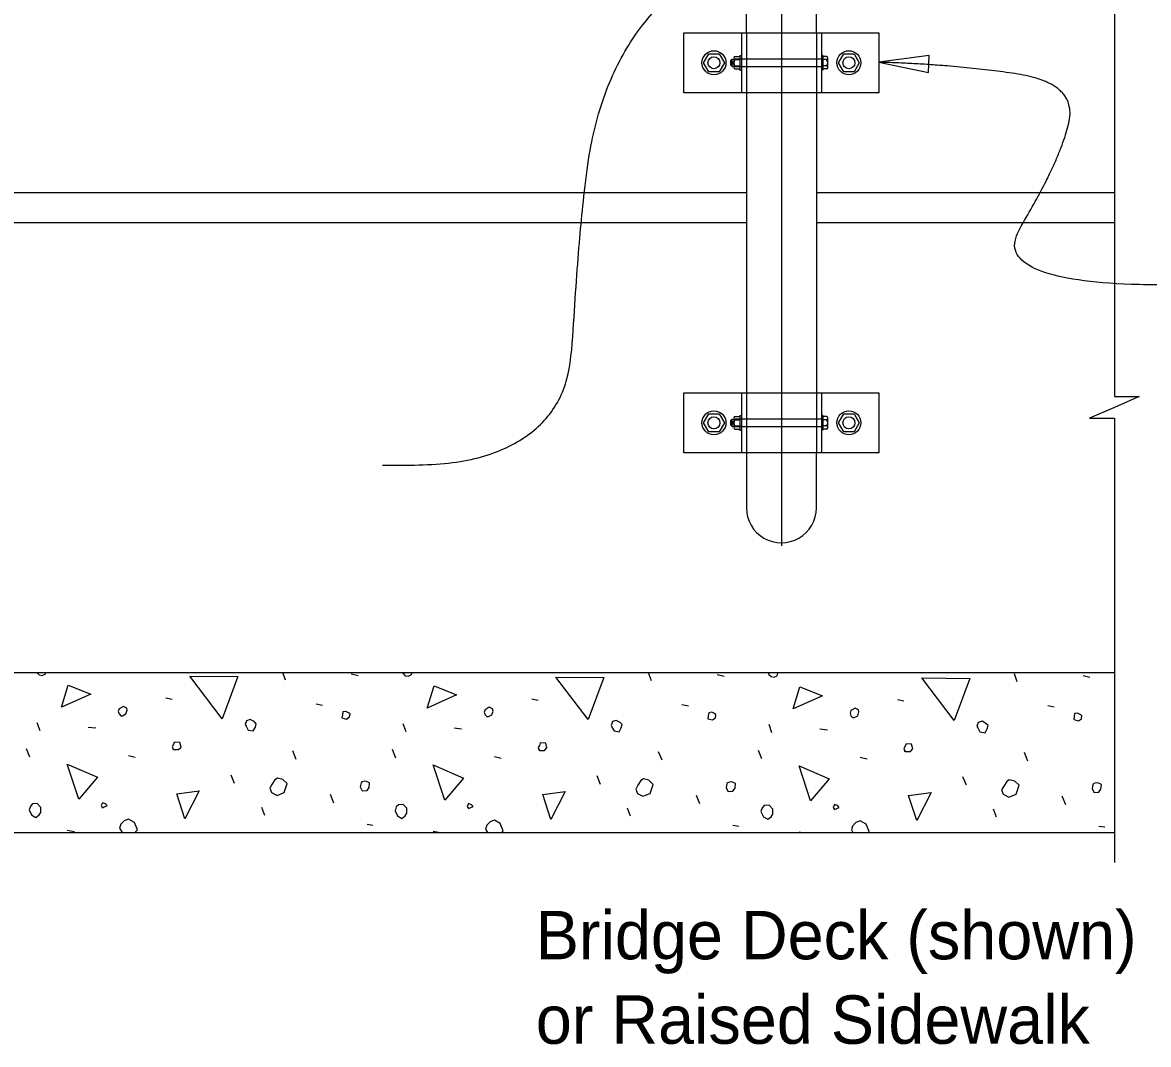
# Model space of a CAD drawing. Extents: x 0 to 72.1, y -7 to 30.
# Drawn here: x 19.062 to 23.751, y 14.64 to 18.897 of the extents above; entities that cross this region are included whole.
import ezdxf

# ---------------------------------------------------------------- set-up
doc = ezdxf.new("R2010")
doc.units = 0
for name, color, linetype in [('AdhocPoint_dp', 7, 'Continuous'), ('Border', 7, 'Continuous'), ('Patterning', 7, 'Continuous'), ('PlotBorder_dp', 7, 'Continuous'), ('SheetBorder_dp', 7, 'Continuous'), ('TextMisc', 7, 'Continuous')]:
    doc.layers.add(name, color=color, linetype=linetype)

msp = doc.modelspace()

# ---------------------------------------------------------------- linework, layer by layer
at = {"layer": 'AdhocPoint_dp'}
for p, q in [((22.0147, 18.7229), (22.0147, 18.735)), ((22.0204, 18.7229), (22.0204, 18.735)), ((22.0147, 17.2229), (22.0147, 17.235)), ((22.0204, 17.2229), (22.0204, 17.235)), ((20.157, 16.1581), (20.1452, 16.1899)), ((20.431, 16.1846), (20.4593, 16.1776)), ((21.6808, 16.1546), (21.6684, 16.1882)), ((21.9548, 16.1811), (21.9831, 16.174)), ((23.2046, 16.151), (23.1922, 16.1846)), ((23.4786, 16.1776), (23.5069, 16.1705)), ((19.6585, 16.0839), (19.685, 16.0786)), ((20.2842, 16.0591), (20.3108, 16.0538)), ((21.1823, 16.0803), (21.2088, 16.075)), ((21.8081, 16.0556), (21.8346, 16.0503)), ((22.7061, 16.0768), (22.7326, 16.0715)), ((23.3319, 16.052), (23.3584, 16.0467)), ((19.1352, 15.946), (19.1228, 15.9796)), ((19.335, 15.9619), (19.3668, 15.9584)), ((20.659, 15.9424), (20.6466, 15.976)), ((20.8588, 15.9584), (20.8906, 15.9548)), ((22.1828, 15.9389), (22.1705, 15.9725)), ((22.3826, 15.9548), (22.4144, 15.9513)), ((19.0928, 15.8364), (19.0786, 15.8717)), ((20.2012, 15.8275), (20.187, 15.8629)), ((20.6166, 15.8328), (20.6024, 15.8682)), ((21.725, 15.824), (21.7108, 15.8594)), ((22.1404, 15.8293), (22.1263, 15.8647)), ((23.2488, 15.8205), (23.2347, 15.8558)), ((19.5029, 15.8435), (19.5312, 15.8364)), ((21.0267, 15.8399), (21.055, 15.8328)), ((22.5505, 15.8364), (22.5788, 15.8293)), ((19.9448, 15.7268), (19.9307, 15.7621)), ((21.4687, 15.7232), (21.4545, 15.7586)), ((22.9925, 15.7197), (22.9783, 15.7551)), ((20.3585, 15.6455), (20.3444, 15.6808)), ((21.8823, 15.6419), (21.8682, 15.6773)), ((23.4061, 15.6384), (23.392, 15.6737)), ((20.0703, 15.5942), (20.058, 15.6278)), ((21.5942, 15.5907), (21.5818, 15.6242)), ((23.118, 15.5871), (23.1056, 15.6207)), ((19.2483, 15.5323), (19.2784, 15.527)), ((20.4964, 15.5571), (20.5211, 15.5535)), ((20.7722, 15.5288), (20.8022, 15.5235)), ((22.0202, 15.5535), (22.0449, 15.55)), ((22.296, 15.5253), (22.3072, 15.5233)), ((23.544, 15.55), (23.5688, 15.5465))]:
    msp.add_line(p, q, dxfattribs=at)
for points in [[(19.1211, 16.1899), (19.1317, 16.1793)], [(19.1317, 16.1793), (19.144, 16.1776), (19.1564, 16.1829), (19.1588, 16.1899)], [(20.6461, 16.1899), (20.6449, 16.1864), (20.6555, 16.1758)], [(20.6555, 16.1758), (20.6679, 16.174), (20.6802, 16.1793), (20.6838, 16.1899)], [(22.171, 16.1899), (22.1687, 16.1829), (22.1793, 16.1723)], [(22.1793, 16.1723), (22.1917, 16.1705), (22.204, 16.1758), (22.2076, 16.1864), (22.2055, 16.1899)], [(19.2236, 16.045), (19.2519, 16.1369), (19.3456, 16.0998), (19.2236, 16.045)], [(19.8936, 15.9972), (19.7592, 16.174), (19.959, 16.1723), (19.8936, 15.9972)], [(20.7474, 16.0414), (20.7757, 16.1334), (20.8694, 16.0962), (20.7474, 16.0414)], [(21.4174, 15.9937), (21.283, 16.1705), (21.4828, 16.1687), (21.4174, 15.9937)], [(22.9412, 15.9902), (22.8069, 16.167), (23.0066, 16.1652), (22.9412, 15.9902)], [(22.2712, 16.0379), (22.2995, 16.1298), (22.3932, 16.0927), (22.2712, 16.0379)], [(19.4711, 16.0096), (19.4781, 16.0096), (19.4923, 16.0167), (19.4976, 16.0326), (19.4958, 16.0414), (19.4817, 16.0485), (19.464, 16.0379), (19.4605, 16.0273), (19.464, 16.0167), (19.4711, 16.0096)], [(20.9949, 16.0061), (21.002, 16.0061), (21.0161, 16.0132), (21.0214, 16.0291), (21.0196, 16.0379), (21.0055, 16.045), (20.9878, 16.0344), (20.9843, 16.0238), (20.9878, 16.0132), (20.9949, 16.0061)], [(22.5187, 16.0026), (22.5258, 16.0026), (22.5399, 16.0096), (22.5452, 16.0255), (22.5435, 16.0344), (22.5293, 16.0414), (22.5116, 16.0308), (22.5081, 16.0202), (22.5116, 16.0096), (22.5187, 16.0026)], [(19.9926, 15.9654), (20.0014, 15.9495), (20.0226, 15.946), (20.0315, 15.9619), (20.035, 15.976), (20.0262, 15.9849), (20.0102, 15.9937), (19.9943, 15.9884), (19.989, 15.9725), (19.9926, 15.9654)], [(20.3921, 16.0008), (20.4115, 15.9955), (20.4239, 16.0043), (20.4257, 16.0167), (20.4221, 16.0202), (20.408, 16.0273), (20.3956, 16.0255), (20.3939, 16.0132), (20.3921, 16.0008)], [(21.5164, 15.9619), (21.5252, 15.946), (21.5464, 15.9424), (21.5553, 15.9584), (21.5588, 15.9725), (21.55, 15.9813), (21.5341, 15.9902), (21.5182, 15.9849), (21.5128, 15.969), (21.5164, 15.9619)], [(21.9159, 15.9972), (21.9353, 15.9919), (21.9477, 16.0008), (21.9495, 16.0132), (21.9459, 16.0167), (21.9318, 16.0238), (21.9194, 16.022), (21.9177, 16.0096), (21.9159, 15.9972)], [(23.4397, 15.9937), (23.4592, 15.9884), (23.4715, 15.9972), (23.4733, 16.0096), (23.4698, 16.0132), (23.4556, 16.0202), (23.4432, 16.0185), (23.4415, 16.0061), (23.4397, 15.9937)], [(23.0402, 15.9584), (23.049, 15.9424), (23.0702, 15.9389), (23.0791, 15.9548), (23.0826, 15.969), (23.0738, 15.9778), (23.0579, 15.9866), (23.042, 15.9813), (23.0367, 15.9654), (23.0402, 15.9584)], [(19.6903, 15.8682), (19.7115, 15.8682), (19.7221, 15.8788), (19.7168, 15.8983), (19.6938, 15.9), (19.6903, 15.8894), (19.685, 15.8806), (19.6903, 15.8682), (19.6867, 15.8717)], [(21.2141, 15.8647), (21.2353, 15.8647), (21.2459, 15.8753), (21.2406, 15.8947), (21.2176, 15.8965), (21.2141, 15.8859), (21.2088, 15.877), (21.2141, 15.8647), (21.2106, 15.8682)], [(22.7379, 15.8611), (22.7591, 15.8611), (22.7697, 15.8717), (22.7644, 15.8912), (22.7414, 15.8929), (22.7379, 15.8823), (22.7326, 15.8735), (22.7379, 15.8611), (22.7344, 15.8647)], [(19.2961, 15.6614), (19.2483, 15.8081), (19.3738, 15.7533), (19.2961, 15.6614)], [(20.8199, 15.6578), (20.7722, 15.8046), (20.8977, 15.7498), (20.8199, 15.6578)], [(22.3437, 15.6543), (22.296, 15.801), (22.4215, 15.7462), (22.3437, 15.6543)], [(20.0986, 15.6897), (20.1216, 15.6773), (20.1517, 15.6897), (20.164, 15.7268), (20.1464, 15.7445), (20.1234, 15.7498), (20.1128, 15.7427), (20.1004, 15.7232), (20.0916, 15.7073), (20.0986, 15.6897)], [(20.4681, 15.7126), (20.4769, 15.6967), (20.4964, 15.6985), (20.5052, 15.7109), (20.507, 15.7303), (20.4946, 15.7356), (20.4858, 15.7374), (20.4752, 15.7339), (20.4716, 15.7303), (20.4681, 15.7126)], [(21.6224, 15.6861), (21.6454, 15.6737), (21.6755, 15.6861), (21.6879, 15.7232), (21.6702, 15.7409), (21.6472, 15.7462), (21.6366, 15.7392), (21.6242, 15.7197), (21.6154, 15.7038), (21.6224, 15.6861)], [(21.9919, 15.7091), (22.0008, 15.6932), (22.0202, 15.695), (22.029, 15.7073), (22.0308, 15.7268), (22.0184, 15.7321), (22.0096, 15.7339), (21.999, 15.7303), (21.9954, 15.7268), (21.9919, 15.7091)], [(23.1463, 15.6826), (23.1692, 15.6702), (23.1993, 15.6826), (23.2117, 15.7197), (23.194, 15.7374), (23.171, 15.7427), (23.1604, 15.7356), (23.148, 15.7162), (23.1392, 15.7003), (23.1463, 15.6826)], [(23.5157, 15.7056), (23.5246, 15.6897), (23.544, 15.6914), (23.5528, 15.7038), (23.5546, 15.7232), (23.5422, 15.7285), (23.5334, 15.7303), (23.5228, 15.7268), (23.5193, 15.7232), (23.5157, 15.7056)], [(19.738, 15.5801), (19.7044, 15.6844), (19.7981, 15.6967), (19.738, 15.5801)], [(21.2618, 15.5765), (21.2282, 15.6808), (21.3219, 15.6932), (21.2618, 15.5765)], [(22.7856, 15.573), (22.7521, 15.6773), (22.8457, 15.6897), (22.7856, 15.573)], [(19.0892, 15.6172), (19.0998, 15.596), (19.1175, 15.5854), (19.1317, 15.596), (19.1387, 15.6066), (19.1387, 15.6278), (19.1228, 15.6437), (19.1034, 15.6419), (19.0945, 15.6331), (19.0892, 15.6172)], [(19.3951, 15.626), (19.4145, 15.6349), (19.4074, 15.6419), (19.3951, 15.6472), (19.3898, 15.6349), (19.3951, 15.626)], [(20.6131, 15.6136), (20.6237, 15.5924), (20.6413, 15.5818), (20.6555, 15.5924), (20.6626, 15.603), (20.6626, 15.6242), (20.6466, 15.6402), (20.6272, 15.6384), (20.6184, 15.6296), (20.6131, 15.6136)], [(20.9189, 15.6225), (20.9383, 15.6313), (20.9313, 15.6384), (20.9189, 15.6437), (20.9136, 15.6313), (20.9189, 15.6225)], [(22.1369, 15.6101), (22.1475, 15.5889), (22.1652, 15.5783), (22.1793, 15.5889), (22.1864, 15.5995), (22.1864, 15.6207), (22.1705, 15.6366), (22.151, 15.6349), (22.1422, 15.626), (22.1369, 15.6101)], [(22.4427, 15.6189), (22.4621, 15.6278), (22.4551, 15.6349), (22.4427, 15.6402), (22.4374, 15.6278), (22.4427, 15.6189)], [(19.5292, 15.5233), (19.54, 15.5341), (19.5276, 15.5641), (19.5029, 15.5783), (19.4852, 15.5712), (19.4711, 15.5571), (19.4658, 15.5412)], [(21.0565, 15.5233), (21.0638, 15.5306), (21.0515, 15.5606), (21.0267, 15.5748), (21.009, 15.5677), (20.9949, 15.5535), (20.9896, 15.5376)], [(22.5839, 15.5233), (22.5876, 15.527), (22.5753, 15.5571), (22.5505, 15.5712), (22.5328, 15.5641), (22.5187, 15.55), (22.5134, 15.5341)], [(19.4658, 15.5412), (19.4769, 15.5233)], [(20.9896, 15.5376), (20.9985, 15.5233)], [(22.5134, 15.5341), (22.5201, 15.5233)]]:
    msp.add_lwpolyline(points, dxfattribs=at)
at = {"layer": 'Border'}
msp.add_lwpolyline([(23.6092, 19.19), (23.6092, 17.3392), (23.7126, 17.3392), (23.6092, 17.2942), (23.5059, 17.2492), (23.6092, 17.2492), (23.6092, 15.3986)], dxfattribs=at)
msp.add_lwpolyline([(22.6282, 18.7321), (22.835, 18.689), (22.8376, 18.7595)], close=True, dxfattribs=at)
for points in [[(20.5616, 17.0529), (21.3209, 17.019), (21.3812, 18.0751), (21.4565, 18.573), (21.6676, 18.9501), (21.9063, 19.0851), (21.9808, 19.1169), (22.0203, 19.1386), (21.998, 19.0004), (21.7311, 19.049)], [(24.0093, 17.8067), (23.0559, 17.7774), (23.3778, 18.3094), (23.4593, 18.6436), (22.9495, 18.722), (22.6282, 18.7321)]]:
    msp.add_open_spline(points, degree=2, dxfattribs=at)
at = {"layer": 'Patterning'}
for p, q in [((22.0764, 18.8548), (22.0764, 18.6048)), ((22.3681, 18.8548), (22.3681, 18.6048)), ((22.3889, 18.7444), (22.024, 18.7444)), ((22.024, 18.7145), (22.3889, 18.7145)), ((22.0764, 17.3548), (22.0764, 17.1048)), ((22.3681, 17.3548), (22.3681, 17.1048)), ((22.3889, 17.2444), (22.024, 17.2444)), ((22.024, 17.2145), (22.3889, 17.2145))]:
    msp.add_line(p, q, dxfattribs=at)
at = {"layer": 'PlotBorder_dp'}
for p, q in [((22.0764, 18.8548), (22.0764, 19.5169)), ((22.3681, 18.8548), (22.3681, 19.5169)), ((21.8163, 18.8548), (22.6282, 18.8548)), ((21.8163, 18.6048), (21.8163, 18.8548)), ((22.0556, 18.8548), (22.0556, 18.6048)), ((22.3889, 18.8548), (22.3889, 18.6048)), ((22.6282, 18.8548), (22.6282, 18.6048)), ((22.049, 18.7601), (22.049, 18.6995)), ((22.049, 18.7601), (22.0556, 18.7601)), ((22.3952, 18.7601), (22.3891, 18.7601)), ((22.3952, 18.7601), (22.3952, 18.6995)), ((22.0118, 18.7378), (22.0175, 18.7444)), ((22.0118, 18.7201), (22.0118, 18.7378)), ((22.0118, 18.7201), (22.0175, 18.7145)), ((22.0175, 18.7444), (22.024, 18.7444)), ((22.0175, 18.7145), (22.0175, 18.7444)), ((22.0175, 18.7145), (22.024, 18.7145)), ((22.024, 18.7477), (22.024, 18.712)), ((22.0287, 18.7428), (22.049, 18.7428)), ((22.0287, 18.7169), (22.049, 18.7169)), ((22.0289, 18.7558), (22.049, 18.7558)), ((22.049, 18.7558), (22.049, 18.7039)), ((22.4099, 18.7558), (22.3952, 18.7558)), ((22.41, 18.7428), (22.3952, 18.7428)), ((22.41, 18.7168), (22.3952, 18.7168)), ((22.415, 18.7104), (22.415, 18.7493)), ((22.029, 18.7039), (22.049, 18.7039)), ((22.049, 18.6995), (22.0556, 18.6995)), ((22.3952, 18.6995), (22.3891, 18.6995)), ((22.4099, 18.7038), (22.3952, 18.7038)), ((22.6282, 18.6048), (21.8163, 18.6048)), ((22.0764, 18.6048), (22.0764, 17.3548)), ((22.3681, 18.6048), (22.3681, 17.3548)), ((21.8163, 17.3548), (22.6282, 17.3548)), ((21.8163, 17.1048), (21.8163, 17.3548)), ((22.0556, 17.3548), (22.0556, 17.1048)), ((22.3889, 17.3548), (22.3889, 17.1048)), ((22.6282, 17.3548), (22.6282, 17.1048)), ((22.0289, 17.2558), (22.049, 17.2558)), ((22.049, 17.2601), (22.049, 17.1995)), ((22.049, 17.2601), (22.0556, 17.2601)), ((22.049, 17.2558), (22.049, 17.2039)), ((22.3952, 17.2601), (22.3891, 17.2601)), ((22.3952, 17.2601), (22.3952, 17.1995)), ((22.0118, 17.2378), (22.0175, 17.2444)), ((22.0118, 17.2201), (22.0118, 17.2378)), ((22.0118, 17.2201), (22.0175, 17.2145)), ((22.0175, 17.2444), (22.024, 17.2444)), ((22.0175, 17.2145), (22.0175, 17.2444)), ((22.0175, 17.2145), (22.024, 17.2145)), ((22.024, 17.2477), (22.024, 17.212)), ((22.0287, 17.2428), (22.049, 17.2428)), ((22.0287, 17.2169), (22.049, 17.2169)), ((22.4099, 17.2558), (22.3952, 17.2558)), ((22.41, 17.2428), (22.3952, 17.2428)), ((22.41, 17.2168), (22.3952, 17.2168)), ((22.415, 17.2104), (22.415, 17.2493)), ((22.029, 17.2039), (22.049, 17.2039)), ((22.049, 17.1995), (22.0556, 17.1995)), ((22.3952, 17.1995), (22.3891, 17.1995)), ((22.4099, 17.2038), (22.3952, 17.2038)), ((22.6282, 17.1048), (21.8163, 17.1048)), ((22.0763, 17.1048), (22.0763, 16.8757)), ((22.368, 16.8757), (22.368, 17.1048))]:
    msp.add_line(p, q, dxfattribs=at)
for points in [[(21.9196, 18.7674), (21.9629, 18.7674), (21.9846, 18.7298), (21.9629, 18.6923), (21.9196, 18.6923), (21.8979, 18.7298)], [(22.4816, 18.7674), (22.5249, 18.7674), (22.5466, 18.7298), (22.5249, 18.6923), (22.4816, 18.6923), (22.4599, 18.7298)], [(21.9196, 17.2674), (21.9629, 17.2674), (21.9846, 17.2298), (21.9629, 17.1923), (21.9196, 17.1923), (21.8979, 17.2298)], [(22.4816, 17.2674), (22.5249, 17.2674), (22.5466, 17.2298), (22.5249, 17.1923), (22.4816, 17.1923), (22.4599, 17.2298)]]:
    msp.add_lwpolyline(points, close=True, dxfattribs=at)
for centre, radius in [((21.9413, 18.7298), 0.05), ((22.5032, 18.7298), 0.05), ((21.9413, 18.7298), 0.025), ((22.5032, 18.7298), 0.025), ((21.9413, 17.2298), 0.05), ((22.5032, 17.2298), 0.05), ((21.9413, 17.2298), 0.025), ((22.5032, 17.2298), 0.025)]:
    msp.add_circle(centre, radius, dxfattribs=at)
for centre, radius, start, end in [((22.0306, 18.7493), 0.00674, 104.4891, 254.1889), ((22.0435, 18.7298), 0.0196, 138.628, 221.372), ((22.0306, 18.7104), 0.00673, 105.7823, 255.5404), ((22.4082, 18.7493), 0.00673, 285.7823, 75.5404), ((22.4082, 18.7104), 0.00674, 284.4891, 74.1889), ((22.3953, 18.7298), 0.0196, 318.628, 41.372), ((22.0306, 17.2493), 0.00674, 104.4891, 254.1889), ((22.0435, 17.2298), 0.0196, 138.628, 221.372), ((22.0306, 17.2104), 0.00673, 105.7823, 255.5404), ((22.4082, 17.2493), 0.00673, 285.7823, 75.5404), ((22.4082, 17.2104), 0.00674, 284.4891, 74.1889), ((22.3953, 17.2298), 0.0196, 318.628, 41.372)]:
    msp.add_arc(centre, radius, start, end, dxfattribs=at)
msp.add_ellipse((22.2222, 16.8757), major_axis=(0, 0.1458), ratio=0.999499, start_param=1.570796, end_param=4.712389, dxfattribs=at)
at = {"layer": 'SheetBorder_dp'}
msp.add_line((22.2222, 27.5581), (22.2222, 16.7178), dxfattribs=at)
at = {"layer": 'TextMisc'}
for p, q in [((12.3681, 18.1899), (22.0764, 18.1899)), ((22.3681, 18.1899), (23.6091, 18.1899)), ((12.3681, 18.0649), (22.0764, 18.0649)), ((22.3681, 18.0649), (23.6091, 18.0649)), ((0.8353, 16.1899), (23.6092, 16.1899)), ((0.8353, 15.5233), (23.6092, 15.5233))]:
    msp.add_line(p, q, dxfattribs=at)

# ---------------------------------------------------------------- texts
at = {"layer": 'Border'}
for s, p in [('Bridge Deck (shown)', (21.1993, 14.9948)), ('or Raised Sidewalk', (21.1993, 14.6428))]:
    msp.add_text(s, height=0.2016, dxfattribs=at).set_placement(p)

doc.saveas('drawing.dxf')
